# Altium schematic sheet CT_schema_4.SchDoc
size 445 x 328 mm
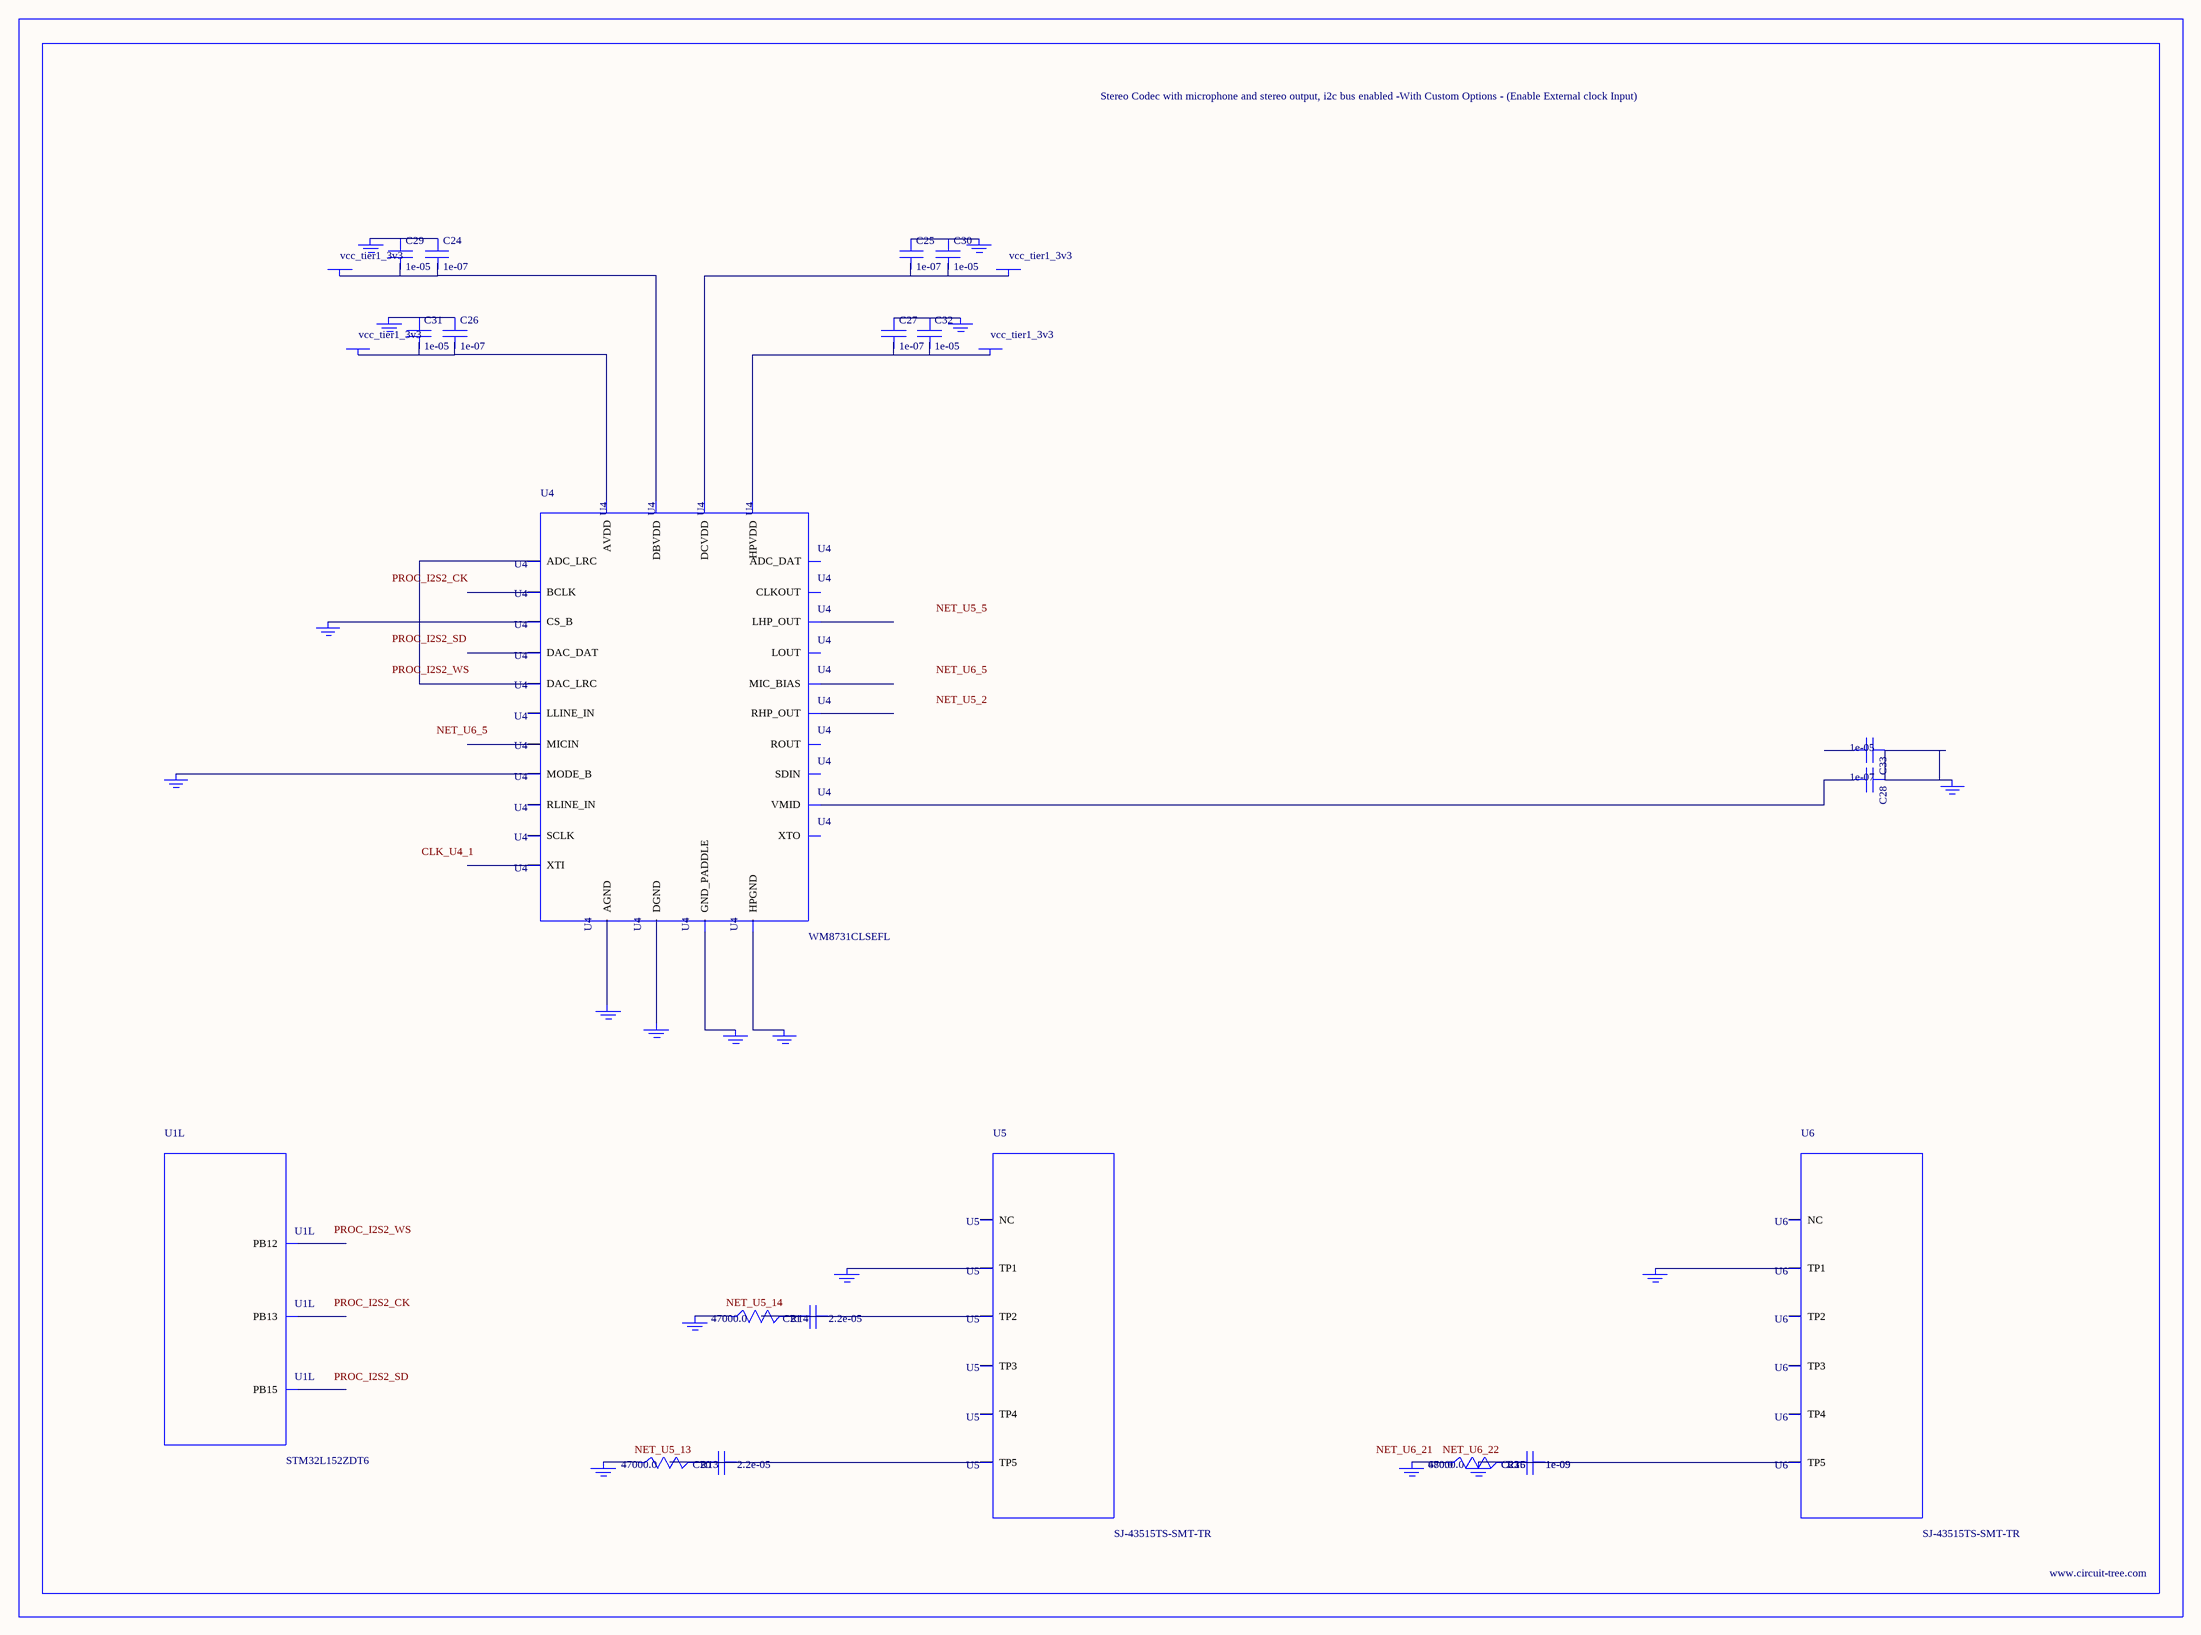
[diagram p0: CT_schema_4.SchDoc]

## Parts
BORDER3  (no value)
C20  2.2e-05  [C1210]
C21  2.2e-05  [C1210]
C22  1e-09  [C0402]
C23  1e-09  [C0402]
C24  1e-07  [C0402]
C25  1e-07  [C0402]
C26  1e-07  [C0402]
C27  1e-07  [C0402]
C28  1e-07  [C0402]
C29  1e-05  [C0805]
C30  1e-05  [C0805]
C31  1e-05  [C0805]
C32  1e-05  [C0805]
C33  1e-05  [C0805]
GND_INSTANCE_3_0  (no value)
GND_INSTANCE_3_1  (no value)
GND_INSTANCE_3_2  (no value)
GND_INSTANCE_3_3  (no value)
GND_INSTANCE_3_4  (no value)
GND_INSTANCE_3_5  (no value)
GND_INSTANCE_3_6  (no value)
GND_INSTANCE_3_7  (no value)
GND_INSTANCE_3_8  (no value)
GND_INSTANCE_3_9  (no value)
GND_INSTANCE_3_10  (no value)
GND_INSTANCE_3_11  (no value)
GND_INSTANCE_3_12  (no value)
GND_INSTANCE_3_13  (no value)
GND_INSTANCE_3_14  (no value)
GND_INSTANCE_3_15  (no value)
GND_INSTANCE_3_16  (no value)
POWER_INSTANCE_3_0  vcc_tier1_3v3
POWER_INSTANCE_3_1  vcc_tier1_3v3
POWER_INSTANCE_3_2  vcc_tier1_3v3
POWER_INSTANCE_3_3  vcc_tier1_3v3
R13  47000.0  [R0603]
R14  47000.0  [R0603]
R15  47000.0  [R0603]
R16  680.0  [R0603]
U1  STM32L152ZDT6  [LQFP144]  (part L of 12)
U4  WM8731CLSEFL  [QFN-28]
U5  SJ-43515TS-SMT-TR  [SJ-43515TS-SMT-TR]
U6  SJ-43515TS-SMT-TR  [SJ-43515TS-SMT-TR]

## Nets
NetC20_1: C20.1 C20.2 R13.2 U5.5(TP5)
NetC21_1: C21.1 C21.2 R14.2 U5.2(TP2)
NetC22_1: C22.1 C22.2 C23.1 C23.2 GND_INSTANCE_3_16.0(GND) R15.2 R16.2 U6.5(TP5)
NetC24_1: C24.1 C29.1 GND_INSTANCE_3_1.0(GND)
NetC24_2: C24.2 C29.2 POWER_INSTANCE_3_1.0(PWR) U4.5(DBVDD)
NetC25_1: C25.1 C30.1 GND_INSTANCE_3_0.0(GND)
NetC25_2: C25.2 C30.2 POWER_INSTANCE_3_0.0(PWR) U4.3(DCVDD)
NetC26_1: C26.1 C31.1 GND_INSTANCE_3_4.0(GND)
NetC26_2: C26.2 C31.2 POWER_INSTANCE_3_3.0(PWR) U4.18(AVDD)
NetC27_1: C27.1 C32.1 GND_INSTANCE_3_2.0(GND)
NetC27_2: C27.2 C32.2 POWER_INSTANCE_3_2.0(PWR) U4.12(HPVDD)
NetC28_1: C28.1 C33.1 GND_INSTANCE_3_5.0(GND)
NetC28_2: C28.2 U4.20(VMID)
NetGND_INSTANCE_3_3_0: GND_INSTANCE_3_3.0(GND) U4.15(HPGND)
NetGND_INSTANCE_3_6_0: GND_INSTANCE_3_6.0(GND) U4.25(MODE_B)
NetGND_INSTANCE_3_7_0: GND_INSTANCE_3_7.0(GND) U4.26(CS_B)
NetGND_INSTANCE_3_8_0: GND_INSTANCE_3_8.0(GND) U4.29(GND_PADDLE)
NetGND_INSTANCE_3_9_0: GND_INSTANCE_3_9.0(GND) U4.4(DGND)
NetGND_INSTANCE_3_10_0: GND_INSTANCE_3_10.0(GND) U4.19(AGND)
NetGND_INSTANCE_3_11_0: GND_INSTANCE_3_11.0(GND) U5.1(TP1)
NetGND_INSTANCE_3_12_0: GND_INSTANCE_3_12.0(GND) R14.1
NetGND_INSTANCE_3_13_0: GND_INSTANCE_3_13.0(GND) R13.1
NetGND_INSTANCE_3_14_0: GND_INSTANCE_3_14.0(GND) U6.1(TP1)
NetGND_INSTANCE_3_15_0: GND_INSTANCE_3_15.0(GND) R15.1 R16.1
NetU4_9: U4.9(DAC_LRC) U4.11(ADC_LRC)

Not connected (* = marked no-connect by the designer): C33 2; U1 73(PB12) 74(PB13) 76(PB15); U4 1(XTI) 2(XTO) 6(CLKOUT) 7(BCLK) 8(DAC_DAT) 10(ADC_DAT) 13(LHP_OUT) 14(RHP_OUT) 16(LOUT) 17(ROUT) 21(MIC_BIAS) 22(MICIN) 23(RLINE_IN) 24(LLINE_IN) 27(SDIN) 28(SCLK); U5 3(TP3) 4(TP4) 6(NC); U6 2(TP2) 3(TP3) 4(TP4) 6(NC)

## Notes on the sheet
- Labels drawn without touching a wire or pin: CLK_U4_1, NET_U5_2, NET_U5_5, NET_U5_13, NET_U5_14, NET_U6_5, NET_U6_21, NET_U6_22, PROC_I2S2_CK, PROC_I2S2_SD, PROC_I2S2_WS

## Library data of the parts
BORDER3 = BORDER_PAGE3
C20 C21 = C1210C224K5RACTU
C22 C23 = C0402C102K3RAC
C24-C28 = C0402C104K3RACTU
C29-C33 = C0805C106K8RACTU
GND_INSTANCE_3_0-GND_INSTANCE_3_16 = GND
POWER_INSTANCE_3_0-POWER_INSTANCE_3_3 = PWR
R13-R15 = RC0603JR-0747KL
R16 = RC0603JR-07680RL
